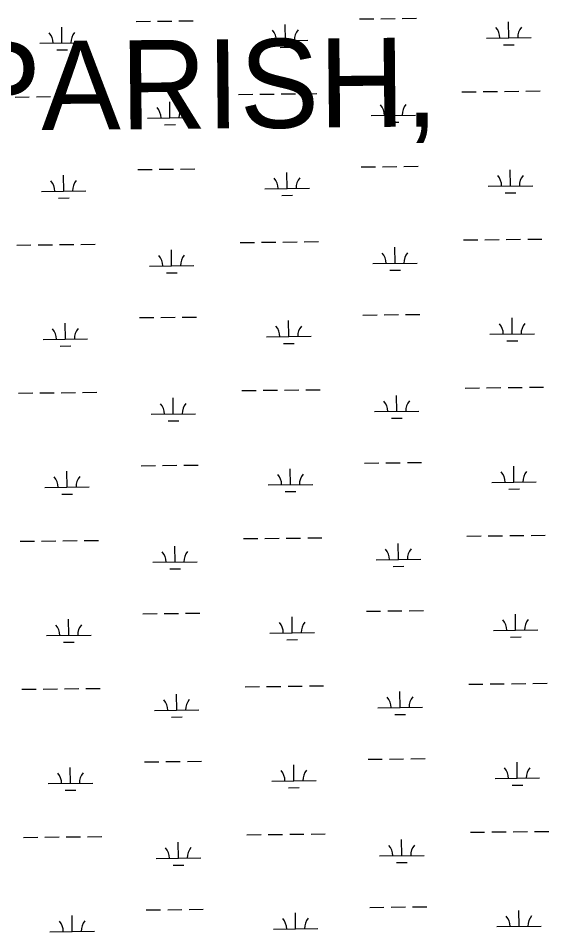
# Model space of a CAD drawing. Extents: x 3678539 to 3716648, y 451386 to 477139.
# Drawn here: x 3685693 to 3686884, y 464892 to 466944 of the extents above; entities that cross this region are included whole.
import ezdxf

# ---------------------------------------------------------------- set-up
doc = ezdxf.new("R2010")
doc.units = 0
doc.layers.add('V-TOPO-GNAM-IDEN', color=7, linetype='Continuous')
doc.layers.add('V-WETL-SWMP', color=7, linetype='Continuous')

msp = doc.modelspace()

# ---------------------------------------------------------------- linework, layer by layer
at = {"layer": 'V-WETL-SWMP'}
for p, q in [((3685957.4, 466936.8), (3685989.4, 466937.2)), ((3686005.4, 466937.3), (3686037.4, 466937.7)), ((3686053.4, 466937.9), (3686085.4, 466938.3)), ((3686292.8, 466894.2), (3686292.3, 466930.2)), ((3686459.3, 466942.5), (3686491.3, 466942.9)), ((3686507.3, 466943.1), (3686539.3, 466943.5)), ((3686555.3, 466943.7), (3686587.3, 466944)), ((3686794.6, 466900), (3686794.2, 466936)), ((3685790.9, 466888.4), (3685790.5, 466924.4)), ((3685740.9, 466887.9), (3685840.9, 466889)), ((3686242.8, 466893.6), (3686342.8, 466894.8)), ((3686744.6, 466899.4), (3686844.6, 466900.5)), ((3685779.1, 466872.9), (3685803.1, 466873.1)), ((3686280.9, 466878.6), (3686304.9, 466878.9)), ((3686782.8, 466884.4), (3686806.8, 466884.7)), ((3685685.4, 466767.1), (3685717.4, 466767.5)), ((3685733.4, 466767.7), (3685765.4, 466768.1)), ((3685781.4, 466768.2), (3685813.4, 466768.6)), ((3685829.4, 466768.8), (3685861.4, 466769.2)), ((3686187.3, 466772.9), (3686219.3, 466773.3)), ((3686235.3, 466773.5), (3686267.3, 466773.8)), ((3686283.3, 466774), (3686315.3, 466774.4)), ((3686331.3, 466774.6), (3686363.3, 466774.9)), ((3686689.2, 466778.7), (3686721.2, 466779)), ((3686737.2, 466779.2), (3686769.2, 466779.6)), ((3686785.2, 466779.8), (3686817.2, 466780.2)), ((3686833.2, 466780.3), (3686865.2, 466780.7)), ((3686033.3, 466720.4), (3686032.9, 466756.4)), ((3686535.2, 466726.2), (3686534.8, 466762.2)), ((3686485.2, 466725.6), (3686585.2, 466726.7)), ((3685983.3, 466719.8), (3686083.3, 466721)), ((3686021.5, 466704.8), (3686045.5, 466705.1)), ((3686523.4, 466710.6), (3686547.4, 466710.9)), ((3685961.2, 466604.1), (3685993.2, 466604.5)), ((3686009.2, 466604.7), (3686041.2, 466605)), ((3686057.2, 466605.2), (3686089.2, 466605.6)), ((3686463.1, 466609.9), (3686495.1, 466610.3)), ((3686511.1, 466610.4), (3686543.1, 466610.8)), ((3686559.1, 466611), (3686591.1, 466611.4)), ((3686798.5, 466567.3), (3686798, 466603.3)), ((3685794.7, 466555.8), (3685794.3, 466591.8)), ((3686296.6, 466561.6), (3686296.2, 466597.5)), ((3686246.6, 466561), (3686346.6, 466562.1)), ((3686748.5, 466566.7), (3686848.5, 466567.9)), ((3685744.7, 466555.2), (3685844.7, 466556.4)), ((3685782.9, 466540.2), (3685806.9, 466540.5)), ((3686284.8, 466546), (3686308.8, 466546.3)), ((3686786.6, 466551.7), (3686810.6, 466552)), ((3686191.1, 466440.3), (3686223.1, 466440.6)), ((3686239.1, 466440.8), (3686271.1, 466441.2)), ((3686287.1, 466441.4), (3686319.1, 466441.7)), ((3686335.1, 466441.9), (3686367.1, 466442.3)), ((3686693, 466446), (3686725, 466446.4)), ((3686741, 466446.6), (3686773, 466446.9)), ((3686789, 466447.1), (3686821, 466447.5)), ((3686837, 466447.7), (3686869, 466448)), ((3685689.2, 466434.5), (3685721.2, 466434.9)), ((3685737.2, 466435), (3685769.2, 466435.4)), ((3685785.2, 466435.6), (3685817.2, 466436)), ((3685833.2, 466436.1), (3685865.2, 466436.5)), ((3686037.1, 466387.7), (3686036.7, 466423.7)), ((3686539, 466393.5), (3686538.6, 466429.5)), ((3685987.1, 466387.2), (3686087.1, 466388.3)), ((3686489, 466392.9), (3686589, 466394.1)), ((3686527.2, 466377.9), (3686551.2, 466378.2)), ((3686025.3, 466372.2), (3686049.3, 466372.5)), ((3686061, 466272.6), (3686093, 466272.9)), ((3686466.9, 466277.2), (3686498.9, 466277.6)), ((3686514.9, 466277.8), (3686546.9, 466278.2)), ((3686562.9, 466278.3), (3686594.9, 466278.7)), ((3685798.5, 466223.1), (3685798.1, 466259.1)), ((3685965, 466271.5), (3685997, 466271.8)), ((3686013, 466272), (3686045, 466272.4)), ((3686300.4, 466228.9), (3686300, 466264.9)), ((3686802.3, 466234.7), (3686801.9, 466270.7)), ((3686752.3, 466234.1), (3686852.3, 466235.2)), ((3685748.5, 466222.6), (3685848.5, 466223.7)), ((3686250.4, 466228.3), (3686350.4, 466229.5)), ((3686288.6, 466213.3), (3686312.6, 466213.6)), ((3686790.5, 466219.1), (3686814.5, 466219.4)), ((3685786.7, 466207.6), (3685810.7, 466207.8)), ((3686290.9, 466108.7), (3686322.9, 466109.1)), ((3686338.9, 466109.3), (3686370.9, 466109.6)), ((3686696.8, 466113.4), (3686728.8, 466113.7)), ((3686744.8, 466113.9), (3686776.8, 466114.3)), ((3686792.8, 466114.5), (3686824.8, 466114.8)), ((3686840.8, 466115), (3686872.8, 466115.4)), ((3685693.1, 466101.8), (3685725.1, 466102.2)), ((3685741.1, 466102.4), (3685773.1, 466102.8)), ((3685789.1, 466102.9), (3685821.1, 466103.3)), ((3685837.1, 466103.5), (3685869.1, 466103.9)), ((3686040.9, 466055.1), (3686040.5, 466091.1)), ((3686194.9, 466107.6), (3686226.9, 466108)), ((3686242.9, 466108.2), (3686274.9, 466108.5)), ((3686542.8, 466060.9), (3686542.4, 466096.9)), ((3685991, 466054.5), (3686090.9, 466055.7)), ((3686492.8, 466060.3), (3686592.8, 466061.4)), ((3686029.1, 466039.5), (3686053.1, 466039.8)), ((3686531, 466045.3), (3686555, 466045.6)), ((3686470.7, 465944.6), (3686502.7, 465945)), ((3686518.7, 465945.1), (3686550.7, 465945.5)), ((3686566.7, 465945.7), (3686598.7, 465946.1)), ((3685802.4, 465890.5), (3685801.9, 465926.5)), ((3685968.9, 465938.8), (3686000.9, 465939.2)), ((3686016.9, 465939.4), (3686048.9, 465939.7)), ((3686064.9, 465939.9), (3686096.9, 465940.3)), ((3686304.2, 465896.2), (3686303.8, 465932.2)), ((3686806.1, 465902), (3686805.7, 465938)), ((3685752.4, 465889.9), (3685852.3, 465891.1)), ((3686254.2, 465895.7), (3686354.2, 465896.8)), ((3686756.1, 465901.4), (3686856.1, 465902.6)), ((3686794.3, 465886.4), (3686818.3, 465886.7)), ((3685790.5, 465874.9), (3685814.5, 465875.2)), ((3686292.4, 465880.7), (3686316.4, 465881)), ((3686700.6, 465780.7), (3686732.6, 465781.1)), ((3686748.6, 465781.3), (3686780.6, 465781.6)), ((3686796.6, 465781.8), (3686828.6, 465782.2)), ((3686844.6, 465782.4), (3686876.6, 465782.7)), ((3685696.9, 465769.2), (3685728.9, 465769.6)), ((3685744.9, 465769.7), (3685776.9, 465770.1)), ((3685792.9, 465770.3), (3685824.9, 465770.7)), ((3685840.9, 465770.8), (3685872.9, 465771.2)), ((3686198.8, 465775), (3686230.8, 465775.3)), ((3686246.8, 465775.5), (3686278.8, 465775.9)), ((3686294.8, 465776.1), (3686326.8, 465776.4)), ((3686342.8, 465776.6), (3686374.8, 465777)), ((3686546.6, 465728.2), (3686546.2, 465764.2)), ((3686044.8, 465722.4), (3686044.4, 465758.4)), ((3685994.8, 465721.9), (3686094.8, 465723)), ((3686496.6, 465727.6), (3686596.6, 465728.8)), ((3686032.9, 465706.9), (3686056.9, 465707.1)), ((3686534.8, 465712.6), (3686558.8, 465712.9)), ((3685972.7, 465606.2), (3686004.7, 465606.5)), ((3686020.7, 465606.7), (3686052.7, 465607.1)), ((3686068.7, 465607.3), (3686100.7, 465607.6)), ((3686308, 465563.6), (3686307.6, 465599.6)), ((3686474.6, 465611.9), (3686506.6, 465612.3)), ((3686522.6, 465612.5), (3686554.6, 465612.9)), ((3686570.6, 465613), (3686602.6, 465613.4)), ((3686809.9, 465569.4), (3686809.5, 465605.4)), ((3685806.2, 465557.8), (3685805.8, 465593.8)), ((3685756.2, 465557.2), (3685856.2, 465558.4)), ((3686258.1, 465563), (3686358, 465564.2)), ((3686759.9, 465568.8), (3686859.9, 465569.9)), ((3685794.4, 465542.3), (3685818.4, 465542.5)), ((3686296.2, 465548), (3686320.2, 465548.3)), ((3686798.1, 465553.8), (3686822.1, 465554.1)), ((3685700.7, 465436.5), (3685732.7, 465436.9)), ((3685748.7, 465437.1), (3685780.7, 465437.5)), ((3685796.7, 465437.6), (3685828.7, 465438)), ((3685844.7, 465438.2), (3685876.7, 465438.6)), ((3686202.6, 465442.3), (3686234.6, 465442.7)), ((3686250.6, 465442.9), (3686282.6, 465443.2)), ((3686298.6, 465443.4), (3686330.6, 465443.8)), ((3686346.6, 465444), (3686378.6, 465444.3)), ((3686704.5, 465448.1), (3686736.5, 465448.4)), ((3686752.5, 465448.6), (3686784.5, 465449)), ((3686800.5, 465449.2), (3686832.5, 465449.5)), ((3686848.5, 465449.7), (3686880.5, 465450.1)), ((3686048.6, 465389.8), (3686048.2, 465425.8)), ((3686550.5, 465395.6), (3686550.1, 465431.6)), ((3686500.5, 465395), (3686600.5, 465396.1)), ((3685998.6, 465389.2), (3686098.6, 465390.4)), ((3686036.8, 465374.2), (3686060.8, 465374.5)), ((3686538.6, 465380), (3686562.6, 465380.3)), ((3685976.5, 465273.5), (3686008.5, 465273.9)), ((3686024.5, 465274.1), (3686056.5, 465274.4)), ((3686072.5, 465274.6), (3686104.5, 465275)), ((3686478.4, 465279.3), (3686510.4, 465279.7)), ((3686526.4, 465279.8), (3686558.4, 465280.2)), ((3686574.4, 465280.4), (3686606.4, 465280.8)), ((3686813.7, 465236.7), (3686813.3, 465272.7)), ((3685810, 465225.2), (3685809.6, 465261.2)), ((3686311.9, 465230.9), (3686311.5, 465266.9)), ((3686261.9, 465230.4), (3686361.9, 465231.5)), ((3686763.7, 465236.1), (3686863.7, 465237.3)), ((3685760, 465224.6), (3685860, 465225.7)), ((3685798.2, 465209.6), (3685822.2, 465209.9)), ((3686300, 465215.4), (3686324, 465215.6)), ((3686801.9, 465221.1), (3686825.9, 465221.4)), ((3685704.5, 465103.9), (3685736.5, 465104.2)), ((3685752.5, 465104.4), (3685784.5, 465104.8)), ((3685800.5, 465105), (3685832.5, 465105.4)), ((3685848.5, 465105.5), (3685880.5, 465105.9)), ((3686206.4, 465109.6), (3686238.4, 465110)), ((3686254.4, 465110.2), (3686286.4, 465110.6)), ((3686302.4, 465110.8), (3686334.4, 465111.1)), ((3686350.4, 465111.3), (3686382.4, 465111.7)), ((3686708.3, 465115.4), (3686740.3, 465115.8)), ((3686756.3, 465116), (3686788.3, 465116.3)), ((3686804.3, 465116.5), (3686836.3, 465116.9)), ((3686852.3, 465117.1), (3686884.3, 465117.4)), ((3686052.4, 465057.1), (3686052, 465093.1)), ((3686554.3, 465062.9), (3686553.9, 465098.9)), ((3686504.3, 465062.3), (3686604.3, 465063.5)), ((3686002.4, 465056.6), (3686102.4, 465057.7)), ((3686040.6, 465041.6), (3686064.6, 465041.8)), ((3686542.5, 465047.3), (3686566.5, 465047.6)), ((3685980.3, 464940.9), (3686012.3, 464941.2)), ((3686028.3, 464941.4), (3686060.3, 464941.8)), ((3686076.3, 464942), (3686108.3, 464942.3)), ((3686482.2, 464946.6), (3686514.2, 464947)), ((3686530.2, 464947.2), (3686562.2, 464947.6)), ((3686578.2, 464947.7), (3686610.2, 464948.1)), ((3686817.6, 464904.1), (3686817.2, 464940)), ((3685813.8, 464892.5), (3685813.4, 464928.5)), ((3686315.7, 464898.3), (3686315.3, 464934.3)), ((3686265.7, 464897.7), (3686365.7, 464898.9)), ((3686767.6, 464903.5), (3686867.6, 464904.6)), ((3685763.8, 464891.9), (3685863.8, 464893.1))]:
    msp.add_line(p, q, dxfattribs=at)
for centre, start, end in [((3685735.6, 466888.3), 359.8865, 41.4302), ((3685846.1, 466889.5), 139.8865, 181.4302), ((3686237.5, 466894), 359.8865, 41.4302), ((3686348, 466895.3), 139.8865, 181.4302), ((3686739.4, 466899.8), 359.8865, 41.4302), ((3686849.9, 466901.1), 139.8865, 181.4302), ((3686479.9, 466726), 359.8865, 41.4302), ((3686590.4, 466727.3), 139.8865, 181.4302), ((3685978.1, 466720.2), 359.8865, 41.4302), ((3686088.5, 466721.5), 139.8865, 181.4302), ((3686241.3, 466561.4), 359.8865, 41.4302), ((3686351.8, 466562.7), 139.8865, 181.4302), ((3686743.2, 466567.2), 359.8865, 41.4302), ((3686853.7, 466568.4), 139.8865, 181.4302), ((3685739.5, 466555.6), 359.8865, 41.4302), ((3685849.9, 466556.9), 139.8865, 181.4302), ((3686483.8, 466393.4), 359.8865, 41.4302), ((3686594.2, 466394.6), 139.8865, 181.4302), ((3685981.9, 466387.6), 359.8865, 41.4302), ((3686092.4, 466388.9), 139.8865, 181.4302), ((3686355.6, 466230), 139.8865, 181.4302), ((3686747, 466234.5), 359.8865, 41.4302), ((3686857.5, 466235.8), 139.8865, 181.4302), ((3685743.3, 466223), 359.8865, 41.4302), ((3685853.8, 466224.2), 139.8865, 181.4302), ((3686245.2, 466228.7), 359.8865, 41.4302), ((3685985.7, 466054.9), 359.8865, 41.4302), ((3686096.2, 466056.2), 139.8865, 181.4302), ((3686487.6, 466060.7), 359.8865, 41.4302), ((3686598.1, 466062), 139.8865, 181.4302), ((3686750.9, 465901.9), 359.8865, 41.4302), ((3686861.3, 465903.1), 139.8865, 181.4302), ((3685747.1, 465890.3), 359.8865, 41.4302), ((3685857.6, 465891.6), 139.8865, 181.4302), ((3686249, 465896.1), 359.8865, 41.4302), ((3686359.5, 465897.4), 139.8865, 181.4302), ((3685989.5, 465722.3), 359.8865, 41.4302), ((3686100, 465723.5), 139.8865, 181.4302), ((3686491.4, 465728), 359.8865, 41.4302), ((3686601.9, 465729.3), 139.8865, 181.4302), ((3685750.9, 465557.7), 359.8865, 41.4302), ((3685861.4, 465558.9), 139.8865, 181.4302), ((3686252.8, 465563.4), 359.8865, 41.4302), ((3686363.3, 465564.7), 139.8865, 181.4302), ((3686754.7, 465569.2), 359.8865, 41.4302), ((3686865.2, 465570.5), 139.8865, 181.4302), ((3685993.3, 465389.6), 359.8865, 41.4302), ((3686103.8, 465390.9), 139.8865, 181.4302), ((3686495.2, 465395.4), 359.8865, 41.4302), ((3686605.7, 465396.7), 139.8865, 181.4302), ((3685754.8, 465225), 359.8865, 41.4302), ((3685865.2, 465226.3), 139.8865, 181.4302), ((3686256.6, 465230.8), 359.8865, 41.4302), ((3686367.1, 465232), 139.8865, 181.4302), ((3686758.5, 465236.5), 359.8865, 41.4302), ((3686869, 465237.8), 139.8865, 181.4302), ((3686499, 465062.7), 359.8865, 41.4302), ((3686609.5, 465064), 139.8865, 181.4302), ((3685997.2, 465057), 359.8865, 41.4302), ((3686107.6, 465058.2), 139.8865, 181.4302), ((3686260.4, 464898.1), 359.8865, 41.4302), ((3686370.9, 464899.4), 139.8865, 181.4302), ((3686762.3, 464903.9), 359.8865, 41.4302), ((3686872.8, 464905.2), 139.8865, 181.4302), ((3685758.6, 464892.4), 359.8865, 41.4302), ((3685869.1, 464893.6), 139.8865, 181.4302)]:
    msp.add_arc(centre, 35.2, start, end, dxfattribs=at)

# ---------------------------------------------------------------- texts
at = {"layer": 'V-TOPO-GNAM-IDEN'}
msp.add_text('PARISH,', height=200, rotation=0.5436, dxfattribs=at).set_placement((3685566.3, 466691))

doc.saveas('drawing.dxf')
